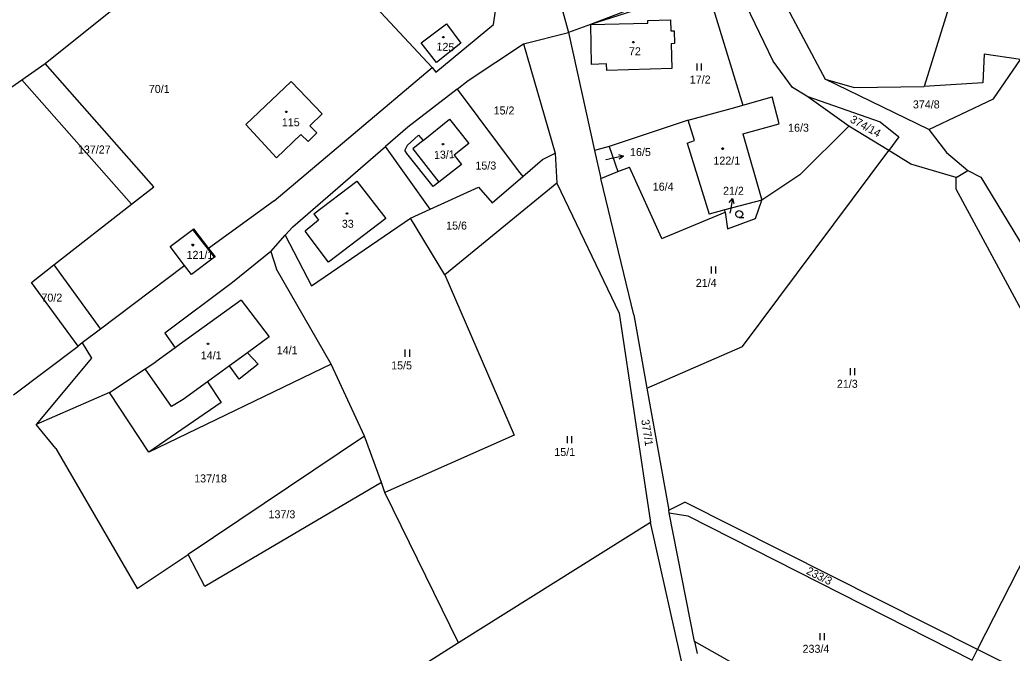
# Model space of a CAD drawing. Extents: x -811039 to -805820, y -1161436 to -1155864.
# Drawn here: x -806771.7 to -806560.9, y -1158370.8 to -1158236.2 of the extents above; entities that cross this region are included whole.
import ezdxf

# ---------------------------------------------------------------- set-up
doc = ezdxf.new("R2010")
doc.units = 0
for name, color, linetype in [('Default', 7, 'Continuous'), ('KN_HRANICE', 7, 'Continuous'), ('KN_KULTURY', 7, 'Continuous'), ('KN_PARCELY', 7, 'Continuous'), ('KN_SLUCKY', 7, 'Continuous')]:
    doc.layers.add(name, color=color, linetype=linetype)

# ---------------------------------------------------------------- blocks, each defined once
blk = doc.blocks.new('304')
at = {"layer": 'Default'}
blk.add_lwpolyline([(0, 0), (-0.38, 0.1), (-0.65, 0.37), (-0.75, 0.74), (-0.65, 1.11), (-0.38, 1.38), (-0.01, 1.48), (0.36, 1.38), (0.63, 1.11), (0.73, 0.73), (0.63, 0.35), (0.36, 0.08), (-0.02, -0.02), (0.98, -0.02)], dxfattribs=at)
blk = doc.blocks.new('306')
at = {"layer": 'Default'}
for p, q in [((-0.5, 1.5), (-0.5, 0)), ((0.5, 0), (0.5, 1.5))]:
    blk.add_line(p, q, dxfattribs=at)
blk = doc.blocks.new('10292')
at = {"layer": 'Default'}
blk.add_line((0, 3), (0, 0), dxfattribs=at)
blk.add_lwpolyline([(-0.5, 2), (0, 3), (0.5, 2)], dxfattribs=at)
blk = doc.blocks.new('402')
at = {"layer": 'Default'}
blk.add_lwpolyline([(0.09, 0.15), (0.18, 0), (0.09, -0.15), (-0.09, -0.15), (-0.18, 0), (-0.09, 0.15), (0.09, 0.15)], dxfattribs=at)

msp = doc.modelspace()

# ---------------------------------------------------------------- linework, layer by layer
at = {"layer": 'KN_HRANICE'}
for p, q in [((-806569.88, -1158219.21), (-806579.62, -1158250.35)), ((-806614.52, -1158222.57), (-806600.61, -1158248.81)), ((-806701.18, -1158227.97), (-806684.08, -1158246.35)), ((-806626.33, -1158227.96), (-806650.49, -1158237.2)), ((-806625.78, -1158229.31), (-806650.49, -1158237.2)), ((-806625.78, -1158229.31), (-806618.07, -1158254.33)), ((-806766.34, -1158245.5), (-806751.34, -1158233.56)), ((-806611.64, -1158244.97), (-806617.42, -1158233.13)), ((-806671.05, -1158237.22), (-806670.66, -1158234.29)), ((-806656.32, -1158234.5), (-806655.17, -1158238.94)), ((-806686.4, -1158241.1), (-806681.08, -1158237.07)), ((-806683.35, -1158247.36), (-806671.05, -1158237.22)), ((-806681.08, -1158237.07), (-806677.98, -1158241.18)), ((-806650.49, -1158237.2), (-806655.17, -1158238.94)), ((-806650.49, -1158237.2), (-806638.26, -1158236.95)), ((-806650.49, -1158237.2), (-806650.31, -1158245.68)), ((-806638.28, -1158236.39), (-806633.47, -1158236.25)), ((-806638.26, -1158236.95), (-806638.28, -1158236.39)), ((-806633.47, -1158236.25), (-806633.41, -1158238.54)), ((-806664.69, -1158241.33), (-806655.17, -1158238.94)), ((-806655.17, -1158238.94), (-806649.62, -1158263.99)), ((-806633.41, -1158238.54), (-806632.7, -1158238.55)), ((-806632.7, -1158238.55), (-806632.65, -1158241.28)), ((-806683.16, -1158245.26), (-806686.4, -1158241.1)), ((-806677.98, -1158241.18), (-806683.16, -1158245.26)), ((-806676.42, -1158249.09), (-806664.69, -1158241.33)), ((-806664.69, -1158241.33), (-806657.99, -1158264.53)), ((-806632.65, -1158241.28), (-806633.35, -1158241.33)), ((-806633.35, -1158241.33), (-806633.22, -1158246.57)), ((-806566.82, -1158243.53), (-806567.15, -1158249.63)), ((-806559.13, -1158244.68), (-806566.82, -1158243.53)), ((-806771.28, -1158248.97), (-806766.34, -1158245.5)), ((-806743.22, -1158271.7), (-806766.34, -1158245.5)), ((-806717.64, -1158274.65), (-806684.08, -1158246.35)), ((-806684.08, -1158246.35), (-806683.35, -1158247.36)), ((-806647.05, -1158245.59), (-806650.31, -1158245.68)), ((-806647.02, -1158246.96), (-806647.05, -1158245.59)), ((-806633.22, -1158246.57), (-806647.02, -1158246.96)), ((-806607.53, -1158250.61), (-806611.64, -1158244.97)), ((-806564.83, -1158253.03), (-806559.13, -1158244.68)), ((-806600.61, -1158248.81), (-806594.47, -1158250.63)), ((-806578.58, -1158259.54), (-806600.61, -1158248.81)), ((-806844.14, -1158300.03), (-806771.28, -1158248.97)), ((-806771.28, -1158248.97), (-806747.96, -1158275.4)), ((-806723.67, -1158258.49), (-806714.03, -1158249.32)), ((-806714.03, -1158249.32), (-806707.44, -1158256.22)), ((-806678.79, -1158250.93), (-806689.25, -1158259.04)), ((-806678.79, -1158250.93), (-806676.42, -1158249.09)), ((-806678.79, -1158250.93), (-806665.8, -1158268.27)), ((-806604.52, -1158252.42), (-806607.53, -1158250.61)), ((-806594.47, -1158250.63), (-806579.62, -1158250.35)), ((-806567.15, -1158249.63), (-806579.62, -1158250.35)), ((-806618.07, -1158254.33), (-806611.9, -1158252.58)), ((-806610.42, -1158258.3), (-806611.9, -1158252.58)), ((-806595.61, -1158258.78), (-806604.52, -1158252.42)), ((-806604.52, -1158252.42), (-806588.94, -1158257.91)), ((-806578.58, -1158259.54), (-806564.83, -1158253.03)), ((-806629.7, -1158257.57), (-806619.79, -1158254.82)), ((-806619.79, -1158254.82), (-806618.07, -1158254.33)), ((-806707.44, -1158256.22), (-806710.08, -1158258.75)), ((-806723.67, -1158258.49), (-806717.14, -1158265.51)), ((-806710.08, -1158258.75), (-806708.63, -1158260.25)), ((-806689.25, -1158259.04), (-806694.03, -1158263.13)), ((-806686.04, -1158261.84), (-806680.41, -1158257.34)), ((-806680.41, -1158257.34), (-806676.3, -1158262.5)), ((-806629.7, -1158257.57), (-806646.48, -1158263.13)), ((-806628.38, -1158261.89), (-806629.7, -1158257.57)), ((-806618.08, -1158260.43), (-806610.42, -1158258.3)), ((-806606.02, -1158269.18), (-806595.61, -1158258.78)), ((-806587.11, -1158264), (-806595.61, -1158258.78)), ((-806588.94, -1158257.91), (-806584.95, -1158261.1)), ((-806711.97, -1158260.56), (-806717.14, -1158265.51)), ((-806710.46, -1158262.04), (-806711.97, -1158260.56)), ((-806708.63, -1158260.25), (-806710.46, -1158262.04)), ((-806689.43, -1158262.92), (-806686.97, -1158260.72)), ((-806686.97, -1158260.72), (-806686.04, -1158261.84)), ((-806618.08, -1158260.43), (-806614.08, -1158274.51)), ((-806584.95, -1158261.1), (-806587.11, -1158264)), ((-806578.58, -1158259.54), (-806574.85, -1158264.38)), ((-806713.73, -1158280.2), (-806694.03, -1158263.13)), ((-806684.52, -1158276.47), (-806694.03, -1158263.13)), ((-806689.43, -1158262.92), (-806689.88, -1158263.88)), ((-806676.3, -1158262.5), (-806679.43, -1158265)), ((-806646.48, -1158263.13), (-806649.62, -1158263.99)), ((-806646.48, -1158263.13), (-806644.64, -1158268.47)), ((-806629.91, -1158262.41), (-806628.38, -1158261.89)), ((-806629.91, -1158262.41), (-806625.23, -1158277.52)), ((-806689.49, -1158264.59), (-806689.88, -1158263.88)), ((-806683.89, -1158271.65), (-806689.49, -1158264.59)), ((-806679.43, -1158265), (-806677.9, -1158266.93)), ((-806660.68, -1158265.92), (-806657.99, -1158264.53)), ((-806657.99, -1158264.53), (-806657.64, -1158270.92)), ((-806649.62, -1158263.99), (-806648.3, -1158269.92)), ((-806618.18, -1158305.63), (-806587.11, -1158264)), ((-806582.39, -1158266.9), (-806587.11, -1158264)), ((-806574.85, -1158264.38), (-806570.3, -1158268.26)), ((-806677.9, -1158266.93), (-806682.66, -1158270.72)), ((-806664.86, -1158269.51), (-806660.68, -1158265.92)), ((-806644.64, -1158268.47), (-806642.16, -1158267.49)), ((-806635.29, -1158282.7), (-806642.16, -1158267.49)), ((-806572.81, -1158269.71), (-806582.39, -1158266.9)), ((-806671.36, -1158275.11), (-806664.86, -1158269.51)), ((-806665.8, -1158268.27), (-806664.86, -1158269.51)), ((-806648.3, -1158269.92), (-806644.64, -1158268.47)), ((-806641.29, -1158298.89), (-806648.3, -1158269.92)), ((-806606.02, -1158269.18), (-806614.08, -1158274.51)), ((-806572.81, -1158269.71), (-806570.3, -1158268.26)), ((-806572.8, -1158272.22), (-806572.81, -1158269.71)), ((-806570.3, -1158268.26), (-806567.55, -1158269.62)), ((-806567.55, -1158269.62), (-806558.32, -1158284.79)), ((-806747.96, -1158275.4), (-806743.22, -1158271.7)), ((-806684.52, -1158276.47), (-806674.23, -1158271.75)), ((-806682.66, -1158270.72), (-806683.89, -1158271.65)), ((-806657.64, -1158270.92), (-806681.44, -1158290.41)), ((-806674.23, -1158271.75), (-806671.36, -1158275.11)), ((-806657.64, -1158270.92), (-806644.38, -1158298.52)), ((-806544.86, -1158324.01), (-806572.8, -1158272.22)), ((-806764.5, -1158288.31), (-806747.96, -1158275.4)), ((-806717.64, -1158274.65), (-806731.62, -1158284.78)), ((-806614.08, -1158274.51), (-806621.9, -1158276.62)), ((-806615.4, -1158278.42), (-806614.08, -1158274.51)), ((-806709.75, -1158292.76), (-806688.67, -1158278.37)), ((-806688.67, -1158278.37), (-806684.52, -1158276.47)), ((-806681.44, -1158290.41), (-806688.67, -1158278.37)), ((-806635.29, -1158282.7), (-806621.84, -1158277.08)), ((-806621.9, -1158276.62), (-806625.23, -1158277.52)), ((-806621.84, -1158277.08), (-806621.9, -1158276.62)), ((-806621.84, -1158277.08), (-806621.36, -1158280.63)), ((-806715.31, -1158282), (-806713.73, -1158280.2)), ((-806621.36, -1158280.63), (-806615.4, -1158278.42)), ((-806739.78, -1158284.38), (-806734.91, -1158280.74)), ((-806734.91, -1158280.74), (-806734.79, -1158280.65)), ((-806734.79, -1158280.65), (-806731.62, -1158284.78)), ((-806718.34, -1158285.46), (-806715.31, -1158282)), ((-806715.31, -1158282), (-806709.75, -1158292.76)), ((-806736.68, -1158288.42), (-806739.78, -1158284.38)), ((-806730.31, -1158286.64), (-806735.22, -1158290.32)), ((-806731.62, -1158284.78), (-806730.19, -1158286.55)), ((-806730.31, -1158286.64), (-806730.19, -1158286.55)), ((-806718.34, -1158285.46), (-806726.53, -1158292.04)), ((-806718.34, -1158285.46), (-806717.16, -1158289.2)), ((-806769.23, -1158292), (-806764.5, -1158288.31)), ((-806764.5, -1158288.31), (-806754.53, -1158301.94)), ((-806736.89, -1158288.6), (-806754.53, -1158301.94)), ((-806736.68, -1158288.42), (-806736.89, -1158288.6)), ((-806735.22, -1158290.32), (-806736.68, -1158288.42)), ((-806705.56, -1158309.37), (-806717.16, -1158289.2)), ((-806681.44, -1158290.41), (-806666.71, -1158324.45)), ((-806759.33, -1158305.54), (-806769.23, -1158292)), ((-806726.53, -1158292.04), (-806740.91, -1158302.82)), ((-806724.7, -1158295.75), (-806737.81, -1158305.26)), ((-806724.7, -1158295.75), (-806718.75, -1158303.59)), ((-806644.38, -1158298.52), (-806637.75, -1158343)), ((-806641.29, -1158298.89), (-806638.49, -1158314.46)), ((-806754.53, -1158301.94), (-806758.42, -1158304.88)), ((-806740.91, -1158302.82), (-806738.67, -1158305.89)), ((-806718.75, -1158303.59), (-806723.3, -1158306.96)), ((-806773.03, -1158315.88), (-806759.33, -1158305.54)), ((-806758.42, -1158304.88), (-806759.33, -1158305.54)), ((-806758.42, -1158304.88), (-806756.43, -1158308.08)), ((-806737.81, -1158305.26), (-806738.67, -1158305.89)), ((-806638.49, -1158314.46), (-806618.18, -1158305.63)), ((-806738.67, -1158305.89), (-806742.78, -1158308.87)), ((-806723.3, -1158306.96), (-806721.06, -1158309.4)), ((-806756.43, -1158308.08), (-806768.24, -1158322.22)), ((-806745.03, -1158310.37), (-806742.78, -1158308.87)), ((-806705.56, -1158309.37), (-806744.29, -1158328.1)), ((-806727.16, -1158309.73), (-806731.85, -1158313.12)), ((-806725.08, -1158312.56), (-806727.16, -1158309.73)), ((-806721.06, -1158309.4), (-806725.08, -1158312.56)), ((-806698.45, -1158324.65), (-806705.56, -1158309.37)), ((-806752.62, -1158315.42), (-806745.03, -1158310.37)), ((-806731.85, -1158313.12), (-806728.91, -1158317.51)), ((-806752.62, -1158315.42), (-806768.24, -1158322.22)), ((-806744.29, -1158328.1), (-806752.62, -1158315.42)), ((-806638.49, -1158314.46), (-806633.84, -1158340.37)), ((-806728.91, -1158317.51), (-806744.29, -1158328.1)), ((-806764.06, -1158327.28), (-806768.24, -1158322.22)), ((-806698.45, -1158324.65), (-806735.95, -1158349.81)), ((-806694.87, -1158334.56), (-806698.45, -1158324.65)), ((-806666.71, -1158324.45), (-806694.12, -1158336.64)), ((-806568.24, -1158369.98), (-806544.86, -1158324.01)), ((-806764.06, -1158327.28), (-806758.94, -1158336.1)), ((-806694.87, -1158334.56), (-806732.36, -1158356.65)), ((-806694.12, -1158336.64), (-806694.87, -1158334.56)), ((-806758.94, -1158336.1), (-806746.75, -1158357.06)), ((-806678.47, -1158368.59), (-806694.12, -1158336.64)), ((-806633.84, -1158340.37), (-806630.46, -1158338.72)), ((-806568.24, -1158369.98), (-806630.46, -1158338.72)), ((-806633.73, -1158341), (-806633.84, -1158340.37)), ((-806628.39, -1158368.28), (-806633.73, -1158341)), ((-806633.73, -1158341), (-806629.79, -1158341.63)), ((-806629.79, -1158341.63), (-806569.41, -1158372.27)), ((-806637.75, -1158343), (-806678.47, -1158368.59)), ((-806624.17, -1158403.51), (-806637.75, -1158343)), ((-806746.75, -1158357.06), (-806735.95, -1158349.81)), ((-806732.36, -1158356.65), (-806735.95, -1158349.81)), ((-806678.47, -1158368.59), (-806701.28, -1158382.95)), ((-806588.22, -1158390.98), (-806628.39, -1158368.28)), ((-806628.39, -1158368.28), (-806627.84, -1158370.88)), ((-806569.41, -1158372.27), (-806568.24, -1158369.98)), ((-806558.16, -1158375.01), (-806568.24, -1158369.98))]:
    msp.add_line(p, q, dxfattribs=at)
at = {"layer": 'KN_PARCELY'}
for p, q in [((-806647.22, -1158265.92), (-806646.4, -1158265.75)), ((-806620.82, -1158277.27), (-806620.8, -1158277.11))]:
    msp.add_line(p, q, dxfattribs=at)
at = {"layer": 'KN_SLUCKY'}
for p, q in [((-806686.04, -1158261.84), (-806688.23, -1158263.6)), ((-806688.23, -1158263.6), (-806682.66, -1158270.72)), ((-806709.22, -1158277.41), (-806700.11, -1158270.52)), ((-806700.11, -1158270.52), (-806693.93, -1158278.43)), ((-806709.22, -1158277.41), (-806708.23, -1158278.8)), ((-806708.23, -1158278.8), (-806711.11, -1158281.13)), ((-806693.93, -1158278.43), (-806706.13, -1158287.7)), ((-806730.31, -1158286.64), (-806734.91, -1158280.74)), ((-806706.13, -1158287.7), (-806711.11, -1158281.13)), ((-806723.3, -1158306.96), (-806727.16, -1158309.73)), ((-806739.44, -1158318.4), (-806745.03, -1158310.37)), ((-806731.85, -1158313.12), (-806737.02, -1158316.88)), ((-806737.02, -1158316.88), (-806739.44, -1158318.4))]:
    msp.add_line(p, q, dxfattribs=at)

# ---------------------------------------------------------------- block references
at = {"layer": 'KN_KULTURY'}
for name, p in [('402', (-806681.72, -1158239.89)), ('402', (-806641.36, -1158240.99)), ('306', (-806627.41, -1158246.98)), ('402', (-806715.07, -1158255.74)), ('402', (-806681.78, -1158262.61)), ('402', (-806622.4, -1158263.59)), ('402', (-806702.18, -1158277.35)), ('304', (-806618.87, -1158278.23)), ('402', (-806734.94, -1158284.07)), ('306', (-806624.32, -1158290.1)), ('402', (-806731.71, -1158305.07)), ('306', (-806689.37, -1158307.79)), ('306', (-806594.81, -1158311.7)), ('306', (-806654.95, -1158326.2)), ('306', (-806601.25, -1158368.01))]:
    msp.add_blockref(name, p, dxfattribs=at)
at = {"layer": 'KN_PARCELY'}
for p, rotation in [((-806646.4, -1158265.75), -78.563131), ((-806620.8, -1158277.11), -8.948759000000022)]:
    msp.add_blockref('10292', p, dxfattribs=dict(at, rotation=rotation))

# ---------------------------------------------------------------- texts
for s, rotation, p in [('125', 356.552, (-806683.24, -1158242.7)), ('374/14', 330.826, (-806595.48, -1158257.86)), ('13/1', 2.578, (-806683.68, -1158265.79)), ('377/1', 278.859, (-806639.69, -1158321.25)), ('233/3', 333.576, (-806604.78, -1158353.86))]:
    msp.add_text(s, height=1.7, rotation=rotation, dxfattribs=at).set_placement(p)
for s, height, p in [('72', 1.7, (-806642.3, -1158243.75)), ('17/2', 1.7, (-806629.38, -1158249.76)), ('70/1', 1.7, (-806744.29, -1158251.75)), ('15/2', 1.7, (-806671.04, -1158256.33)), ('374/8', 1.7, (-806581.98, -1158255.04)), ('115', 1.7, (-806716.03, -1158258.83)), ('16/3', 1.7, (-806608.49, -1158259.99)), ('137/27', 1.7, (-806759.35, -1158264.62)), ('16/5', 1.7, (-806642.07, -1158265.16)), ('122/1', 1.7, (-806624.36, -1158266.98)), ('15/3', 1.7, (-806674.91, -1158268.03)), ('16/5', 0.1, (-806647.42, -1158265.92)), ('16/4', 1.7, (-806637.24, -1158272.51)), ('21/2', 1.7, (-806622.32, -1158273.39)), ('21/2', 0.1, (-806621.02, -1158277.27)), ('33', 1.7, (-806703.29, -1158280.4)), ('15/6', 1.7, (-806681.13, -1158280.79)), ('121/1', 1.7, (-806736.27, -1158287.01)), ('21/4', 1.7, (-806628.1, -1158292.96)), ('70/2', 1.7, (-806767.1, -1158296.09)), ('14/1', 1.7, (-806717.11, -1158307.26)), ('14/1', 1.7, (-806733.25, -1158308.35)), ('15/5', 1.7, (-806692.81, -1158310.49)), ('21/3', 1.7, (-806598.13, -1158314.4)), ('15/1', 1.7, (-806658.15, -1158328.9)), ('137/18', 1.7, (-806734.65, -1158334.51)), ('137/3', 1.7, (-806718.86, -1158342.13)), ('233/4', 1.7, (-806605.42, -1158370.71))]:
    msp.add_text(s, height=height, dxfattribs=at).set_placement(p)

doc.saveas('drawing.dxf')
